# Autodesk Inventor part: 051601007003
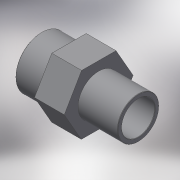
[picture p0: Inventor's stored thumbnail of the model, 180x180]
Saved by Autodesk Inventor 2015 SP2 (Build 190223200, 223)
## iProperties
Created: 2017-10
Part Number: 051601007003
Material: Generic
Description: PLASSON THR. REDUCING NIPPLE 3/4"-3/8" PVC
Document SubType Name: Modeling
Designer: KIM
Density: 1 g/cm^3
Appearance: Default
Author: KIM
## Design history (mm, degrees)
derived "051601.ipt"
feature "Solid1::051601.ipt"
tag "TaggingFeature1"
body "Solid1"
other parameters: "d0" = 45, "d13" = 0, "d14" = 0.16662, "d17" = 16, "d18" = 20.4, "d19" = 26.441, "d21" = 16.662, "d23" = 21.1528, "d24" = 13.3296, "d25" = 17, "d26" = -16, "R_1" = 16.662, "lt_1" = 16, "lt_" = 17, "H_" = 45, "R_" = 26.441
